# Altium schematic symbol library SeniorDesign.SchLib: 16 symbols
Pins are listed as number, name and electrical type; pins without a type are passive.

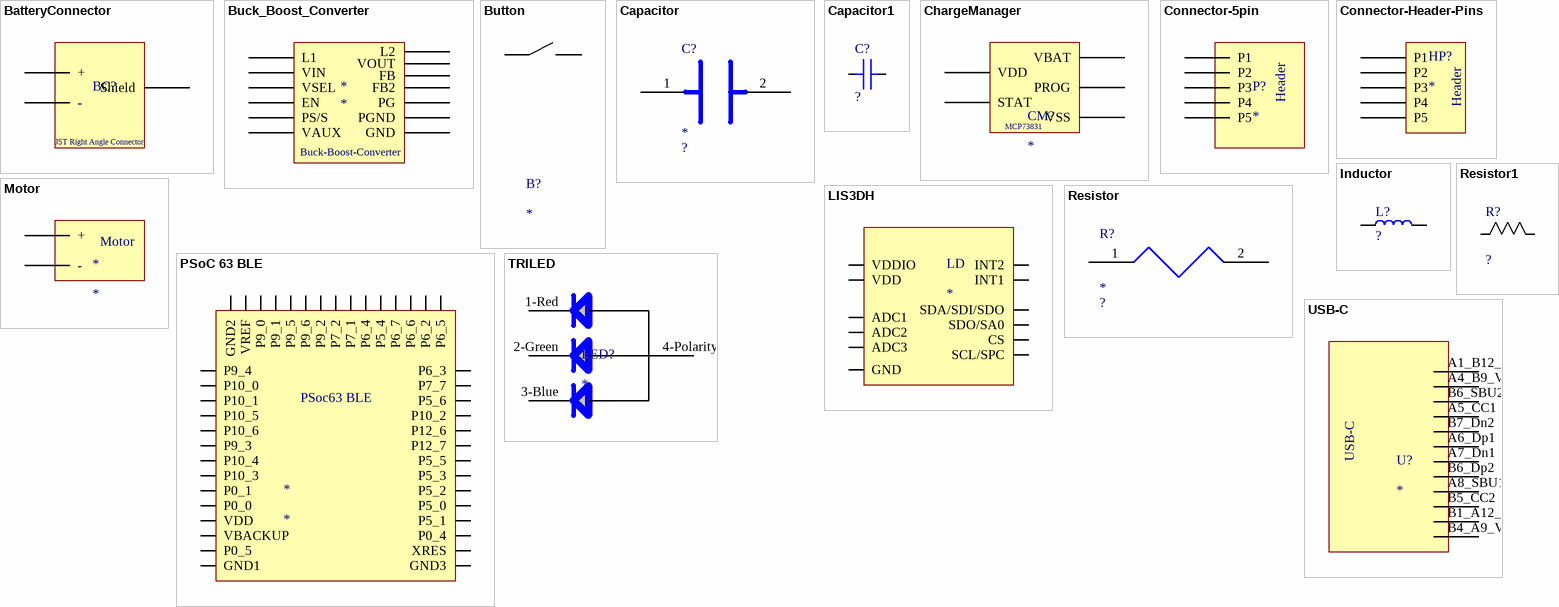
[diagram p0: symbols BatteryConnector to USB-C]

## BatteryConnector
designator BC?  (value not drawn)
footprint JST-Right-Angle-Connector-Team-7
pins: P1 +, P2 -, Shield

## Buck_Boost_Converter
designator *
footprint Buck_Boost_Converter (Buck Boost Converter)
pins: EN, FB, FB2, GND, L1, L2, PG, PGND, PS/S, VAUX, VIN, VOUT, VSEL

## Button
designator B?
Button
footprint BUTTON
pins: B1 1, B3 3

## Capacitor
designator C?
footprint PASSIVE-CAPACITOR-0603
pins: 1, 2

## Capacitor1
designator C?  (value not drawn)
footprint PASSIVE-CAPACITOR-0603
pins: 1, 2

## ChargeManager
designator CM?
footprint Charger-Manager-Team-7
pins: PROG, STAT, VBAT, VDD, VSS

## Connector-5pin
designator P?
footprint CONNECTOR-HEADER-PINS
pins: 1 P1, 2 P2, 3 P3, 4 P4, 5 P5

## Connector-Header-Pins
designator HP?
footprint CONNECTOR-HEADER-PINS
pins: 1 P1, 2 P2, 3 P3, 4 P4, 5 P5

## Inductor
designator L?  (value not drawn)
footprint PASSIVE-INDUCTOR-0603 (Inductor)
pins: 1, 2

## LIS3DH
designator LD
LIS3DH
footprint LIS3DH
pins: ADC1, ADC2, ADC3, CS, GND, INT1, INT2, SCL/SPC, SDA/SDI/SDO, SDO/SA0, VDD, VDDIO

## Motor
designator *
footprint Motor
pins: 1 +, 2 -

## PSoC 63 BLE
designator *
footprint PSoC-63 BLE
pins: 1 GND1, 2 P0_5, 3 VBACKUP, 4 VDD, 5 P0_0, 6 P0_1, 7 P10_3, 8 P10_4, 9 P9_3, 10 P10_6, 11 P10_5, 12 P10_1, 13 P10_0, 14 P9_4, 15 GND2, 16 VREF, 17 P9_0, 18 P9_1, 19 P9_5, 20 P9_6, 21 P9_2, 22 P7_2, 23 P7_1, 24 P6_4, 25 P5_4, 26 P6_7, 27 P6_6, 28 P6_2, 29 P6_5, 30 P6_3, 31 P7_7, 32 P5_6, 33 P10_2, 34 P12_6, 35 P12_7, 36 P5_5, 37 P5_3, 38 P5_2, 39 P5_0, 40 P5_1, 41 P0_4, 42 XRES, 43 GND3

## Resistor
designator R?
footprint Passive-Resistor
pins: 1, 2

## Resistor1
designator R?, comment Resistor  (value not drawn)
footprint PASSIVE-RESISTOR-0603
pins: 1, 2

## TRILED
designator LED?
footprint LTST-C19HE1WT-Team-7
pins: 1-Red, 2-Green, 3-Blue, 4-Polarity

## USB-C
designator U?
footprint USB-C-Team-7
pins: A1_B12_GND, A4_B9_VBUS, A5_CC1, A6_Dp1, A7_Dn1, A8_SBU1, B1_A12_GND, B4_A9_VBUS, B5_CC2, B6_Dp2, B6_SBU2, B7_Dn2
